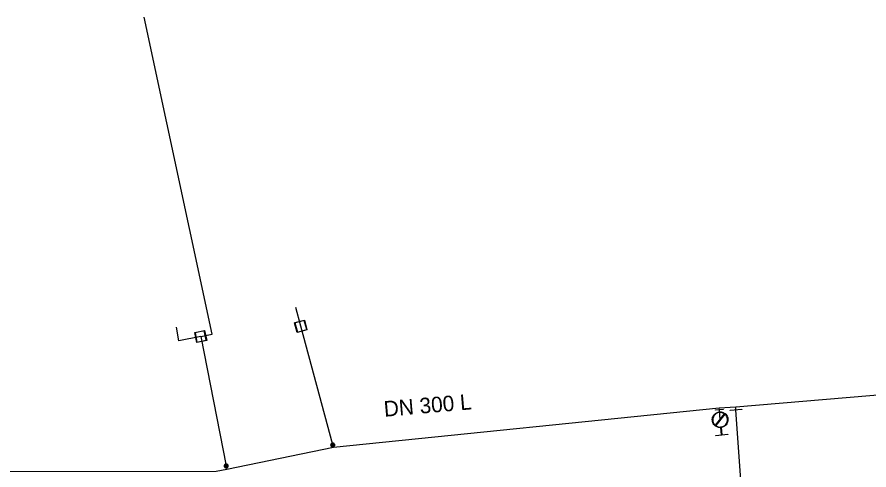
# Model space of a CAD drawing. Extents: x -832382 to -831581, y -1074670 to -1074251.
# Drawn here: x -831981.6 to -831872.2, y -1074329 to -1074270.9 of the extents above; entities that cross this region are included whole.
import ezdxf

# ---------------------------------------------------------------- set-up
doc = ezdxf.new("R2010")
doc.units = 0
for name, color, linetype in [('Hyd-odbočka', 7, 'Continuous'), ('Hyd-šoupě', 7, 'Continuous'), ('Hydrant', 7, 'Continuous'), ('Přípojka vodovodu', 7, 'Continuous'), ('Přípojkový uzávěr', 7, 'Continuous'), ('Roz-řad', 7, 'Continuous'), ('Roz-řad-popis základní', 7, 'Continuous'), ('Řad-šoupě', 7, 'Continuous'), ('Šachta vodovodní', 7, 'Continuous')]:
    doc.layers.add(name, color=color, linetype=linetype)

msp = doc.modelspace()

# ---------------------------------------------------------------- linework, layer by layer
at = {"layer": 'Hyd-odbočka'}
for p, q in [((-831891.44, -1074321.27), (-831891.46, -1074321.09)), ((-831891.35, -1074322.57), (-831891.44, -1074321.27))]:
    msp.add_line(p, q, dxfattribs=at)
at = {"layer": 'Hyd-šoupě'}
msp.add_lwpolyline([(-831891.94, -1074321.29), (-831890.94, -1074321.22), (-831890.94, -1074321.25), (-831891.94, -1074321.32), (-831891.94, -1074321.29)], dxfattribs=at)
at = {"layer": 'Hydrant'}
for points in [[(-831891.96, -1074323.28), (-831890.78, -1074321.82)], [(-831890.74, -1074321.86), (-831891.92, -1074323.32)], [(-831891.21, -1074323.56), (-831891.12, -1074324.49), (-831890.37, -1074324.41), (-831890.36, -1074324.48), (-831891.92, -1074324.64), (-831891.92, -1074324.58), (-831891.18, -1074324.5), (-831891.28, -1074323.57)]]:
    msp.add_lwpolyline(points, dxfattribs=at)
for points in [[(-831891.28, -1074323.57), (-831891.51, -1074323.58), (-831891.75, -1074323.49), (-831892, -1074323.38), (-831892.16, -1074323.16), (-831892.32, -1074322.94), (-831892.34, -1074322.68), (-831892.37, -1074322.42), (-831892.27, -1074322.17), (-831892.16, -1074321.92), (-831891.94, -1074321.76), (-831891.71, -1074321.6), (-831891.46, -1074321.58), (-831891.2, -1074321.55), (-831890.95, -1074321.65), (-831890.7, -1074321.76), (-831890.54, -1074321.98), (-831890.38, -1074322.21), (-831890.36, -1074322.46), (-831890.33, -1074322.73), (-831890.44, -1074322.98), (-831890.55, -1074323.23), (-831890.77, -1074323.38), (-831890.98, -1074323.53), (-831891.21, -1074323.56)], [(-831890.78, -1074321.82), (-831890.87, -1074321.76), (-831890.97, -1074321.71), (-831891.21, -1074321.61), (-831891.45, -1074321.64), (-831891.69, -1074321.66), (-831891.9, -1074321.81), (-831892.11, -1074321.96), (-831892.21, -1074322.19), (-831892.31, -1074322.43), (-831892.28, -1074322.67), (-831892.26, -1074322.91), (-831892.11, -1074323.12), (-831892.04, -1074323.21), (-831891.96, -1074323.28)], [(-831891.92, -1074323.32), (-831891.83, -1074323.39), (-831891.72, -1074323.43), (-831891.49, -1074323.53), (-831891.25, -1074323.5), (-831891.02, -1074323.48), (-831890.81, -1074323.33), (-831890.6, -1074323.19), (-831890.49, -1074322.95), (-831890.39, -1074322.72), (-831890.42, -1074322.47), (-831890.44, -1074322.23), (-831890.59, -1074322.02), (-831890.65, -1074321.93), (-831890.74, -1074321.86)]]:
    msp.add_open_spline(points, degree=3, dxfattribs=at)
at = {"layer": 'Přípojka vodovodu'}
for p, q in [((-831956.59, -1074311.57), (-831965.3, -1074270.86)), ((-831945.19, -1074310.57), (-831945.84, -1074308.15)), ((-831960.87, -1074312.43), (-831961.17, -1074310.68)), ((-831958.05, -1074311.87), (-831960.87, -1074312.43)), ((-831958.05, -1074311.87), (-831956.59, -1074311.57))]:
    msp.add_line(p, q, dxfattribs=at)
for points in [[(-831941.01, -1074326.13), (-831941.09, -1074325.81), (-831945.19, -1074310.57)], [(-831958.05, -1074311.87), (-831954.77, -1074328.5), (-831954.69, -1074328.95)]]:
    msp.add_lwpolyline(points, dxfattribs=at)
at = {"layer": 'Přípojkový uzávěr'}
for points in [[(-831941.09, -1074325.56), (-831941.03, -1074325.56), (-831940.97, -1074325.6), (-831940.91, -1074325.63), (-831940.87, -1074325.69), (-831940.84, -1074325.75), (-831940.84, -1074325.81), (-831940.84, -1074325.88), (-831940.87, -1074325.94), (-831940.91, -1074326), (-831940.97, -1074326.03), (-831941.03, -1074326.06), (-831941.09, -1074326.06), (-831941.15, -1074326.06), (-831941.21, -1074326.03), (-831941.27, -1074326), (-831941.31, -1074325.94), (-831941.34, -1074325.88), (-831941.34, -1074325.81), (-831941.34, -1074325.75), (-831941.31, -1074325.69), (-831941.27, -1074325.63), (-831941.21, -1074325.6), (-831941.15, -1074325.56), (-831941.09, -1074325.56)], [(-831941.09, -1074325.59), (-831941.15, -1074325.59), (-831941.2, -1074325.62), (-831941.26, -1074325.65), (-831941.29, -1074325.7), (-831941.32, -1074325.75), (-831941.32, -1074325.81), (-831941.32, -1074325.87), (-831941.29, -1074325.93), (-831941.26, -1074325.98), (-831941.2, -1074326.01), (-831941.15, -1074326.04), (-831941.09, -1074326.04), (-831941.03, -1074326.04), (-831940.98, -1074326.01), (-831940.92, -1074325.98), (-831940.89, -1074325.93), (-831940.86, -1074325.87), (-831940.86, -1074325.81), (-831940.86, -1074325.75), (-831940.89, -1074325.7), (-831940.92, -1074325.65), (-831940.98, -1074325.62), (-831941.03, -1074325.59), (-831941.09, -1074325.59)], [(-831941.09, -1074325.6), (-831941.04, -1074325.6), (-831940.99, -1074325.63), (-831940.94, -1074325.66), (-831940.91, -1074325.71), (-831940.88, -1074325.76), (-831940.88, -1074325.81), (-831940.88, -1074325.87), (-831940.91, -1074325.92), (-831940.94, -1074325.97), (-831940.99, -1074326), (-831941.04, -1074326.02), (-831941.09, -1074326.02), (-831941.14, -1074326.02), (-831941.19, -1074326), (-831941.24, -1074325.97), (-831941.27, -1074325.92), (-831941.3, -1074325.87), (-831941.3, -1074325.81), (-831941.3, -1074325.76), (-831941.27, -1074325.71), (-831941.24, -1074325.66), (-831941.19, -1074325.63), (-831941.14, -1074325.6), (-831941.09, -1074325.6)], [(-831941.09, -1074325.63), (-831941.17, -1074325.63), (-831941.22, -1074325.68), (-831941.28, -1074325.74), (-831941.28, -1074325.81), (-831941.28, -1074325.89), (-831941.22, -1074325.95), (-831941.17, -1074326), (-831941.09, -1074326), (-831941.01, -1074326), (-831940.96, -1074325.95), (-831940.9, -1074325.89), (-831940.9, -1074325.81), (-831940.9, -1074325.74), (-831940.96, -1074325.68), (-831941.01, -1074325.63), (-831941.09, -1074325.63)], [(-831941.09, -1074325.65), (-831941.02, -1074325.65), (-831940.97, -1074325.7), (-831940.93, -1074325.74), (-831940.93, -1074325.81), (-831940.93, -1074325.88), (-831940.97, -1074325.93), (-831941.02, -1074325.98), (-831941.09, -1074325.98), (-831941.16, -1074325.98), (-831941.21, -1074325.93), (-831941.25, -1074325.88), (-831941.25, -1074325.81), (-831941.25, -1074325.74), (-831941.21, -1074325.7), (-831941.16, -1074325.65), (-831941.09, -1074325.65)], [(-831941.09, -1074325.67), (-831941.15, -1074325.67), (-831941.19, -1074325.71), (-831941.23, -1074325.75), (-831941.23, -1074325.81), (-831941.23, -1074325.87), (-831941.19, -1074325.92), (-831941.15, -1074325.96), (-831941.09, -1074325.96), (-831941.03, -1074325.96), (-831940.99, -1074325.92), (-831940.95, -1074325.87), (-831940.95, -1074325.81), (-831940.95, -1074325.75), (-831940.99, -1074325.71), (-831941.03, -1074325.67), (-831941.09, -1074325.67)], [(-831941.09, -1074325.69), (-831941.04, -1074325.69), (-831941, -1074325.73), (-831940.97, -1074325.76), (-831940.97, -1074325.81), (-831940.97, -1074325.87), (-831941, -1074325.9), (-831941.04, -1074325.94), (-831941.09, -1074325.94), (-831941.14, -1074325.94), (-831941.18, -1074325.9), (-831941.22, -1074325.87), (-831941.22, -1074325.81), (-831941.22, -1074325.76), (-831941.18, -1074325.73), (-831941.14, -1074325.69), (-831941.09, -1074325.69)], [(-831941.09, -1074325.71), (-831941.13, -1074325.71), (-831941.16, -1074325.74), (-831941.19, -1074325.77), (-831941.19, -1074325.81), (-831941.19, -1074325.86), (-831941.16, -1074325.89), (-831941.13, -1074325.91), (-831941.09, -1074325.91), (-831941.05, -1074325.91), (-831941.02, -1074325.89), (-831940.99, -1074325.86), (-831940.99, -1074325.81), (-831940.99, -1074325.77), (-831941.02, -1074325.74), (-831941.05, -1074325.71), (-831941.09, -1074325.71)], [(-831941.09, -1074325.73), (-831941.06, -1074325.73), (-831941.03, -1074325.75), (-831941.01, -1074325.78), (-831941.01, -1074325.81), (-831941.01, -1074325.85), (-831941.03, -1074325.87), (-831941.06, -1074325.9), (-831941.09, -1074325.9), (-831941.13, -1074325.9), (-831941.15, -1074325.87), (-831941.17, -1074325.85), (-831941.17, -1074325.81), (-831941.17, -1074325.78), (-831941.15, -1074325.75), (-831941.13, -1074325.73), (-831941.09, -1074325.73)], [(-831941.09, -1074325.75), (-831941.12, -1074325.75), (-831941.13, -1074325.77), (-831941.15, -1074325.79), (-831941.15, -1074325.81), (-831941.15, -1074325.84), (-831941.13, -1074325.86), (-831941.12, -1074325.88), (-831941.09, -1074325.88), (-831941.06, -1074325.88), (-831941.05, -1074325.86), (-831941.03, -1074325.84), (-831941.03, -1074325.81), (-831941.03, -1074325.79), (-831941.05, -1074325.77), (-831941.06, -1074325.75), (-831941.09, -1074325.75)], [(-831941.09, -1074325.77), (-831941.07, -1074325.77), (-831941.06, -1074325.79), (-831941.05, -1074325.8), (-831941.05, -1074325.81), (-831941.05, -1074325.83), (-831941.06, -1074325.84), (-831941.07, -1074325.85), (-831941.09, -1074325.85), (-831941.11, -1074325.85), (-831941.12, -1074325.84), (-831941.13, -1074325.83), (-831941.13, -1074325.81), (-831941.13, -1074325.8), (-831941.12, -1074325.79), (-831941.11, -1074325.77), (-831941.09, -1074325.77)], [(-831941.09, -1074325.79), (-831941.1, -1074325.79), (-831941.11, -1074325.8), (-831941.11, -1074325.8), (-831941.11, -1074325.81), (-831941.11, -1074325.82), (-831941.11, -1074325.83), (-831941.1, -1074325.84), (-831941.09, -1074325.84), (-831941.08, -1074325.84), (-831941.07, -1074325.83), (-831941.07, -1074325.82), (-831941.07, -1074325.81), (-831941.07, -1074325.8), (-831941.07, -1074325.8), (-831941.08, -1074325.79), (-831941.09, -1074325.79)], [(-831954.77, -1074328.25), (-831954.71, -1074328.25), (-831954.65, -1074328.28), (-831954.59, -1074328.32), (-831954.56, -1074328.38), (-831954.52, -1074328.44), (-831954.52, -1074328.5), (-831954.52, -1074328.57), (-831954.56, -1074328.63), (-831954.59, -1074328.68), (-831954.65, -1074328.72), (-831954.71, -1074328.75), (-831954.77, -1074328.75), (-831954.84, -1074328.75), (-831954.9, -1074328.72), (-831954.96, -1074328.68), (-831954.99, -1074328.63), (-831955.02, -1074328.57), (-831955.02, -1074328.5), (-831955.02, -1074328.44), (-831954.99, -1074328.38), (-831954.96, -1074328.32), (-831954.9, -1074328.28), (-831954.84, -1074328.25), (-831954.77, -1074328.25)], [(-831954.77, -1074328.27), (-831954.83, -1074328.27), (-831954.89, -1074328.3), (-831954.94, -1074328.33), (-831954.97, -1074328.39), (-831955, -1074328.44), (-831955, -1074328.5), (-831955, -1074328.56), (-831954.97, -1074328.61), (-831954.94, -1074328.67), (-831954.89, -1074328.7), (-831954.83, -1074328.73), (-831954.77, -1074328.73), (-831954.72, -1074328.73), (-831954.66, -1074328.7), (-831954.61, -1074328.67), (-831954.58, -1074328.61), (-831954.55, -1074328.56), (-831954.55, -1074328.5), (-831954.55, -1074328.44), (-831954.58, -1074328.39), (-831954.61, -1074328.33), (-831954.66, -1074328.3), (-831954.72, -1074328.27), (-831954.77, -1074328.27)], [(-831954.77, -1074328.29), (-831954.72, -1074328.29), (-831954.67, -1074328.32), (-831954.62, -1074328.35), (-831954.59, -1074328.4), (-831954.56, -1074328.45), (-831954.56, -1074328.5), (-831954.56, -1074328.56), (-831954.59, -1074328.61), (-831954.62, -1074328.66), (-831954.67, -1074328.68), (-831954.72, -1074328.71), (-831954.77, -1074328.71), (-831954.83, -1074328.71), (-831954.88, -1074328.68), (-831954.93, -1074328.66), (-831954.96, -1074328.61), (-831954.98, -1074328.56), (-831954.98, -1074328.5), (-831954.98, -1074328.45), (-831954.96, -1074328.4), (-831954.93, -1074328.35), (-831954.88, -1074328.32), (-831954.83, -1074328.29), (-831954.77, -1074328.29)], [(-831954.77, -1074328.31), (-831954.85, -1074328.31), (-831954.91, -1074328.37), (-831954.96, -1074328.42), (-831954.96, -1074328.5), (-831954.96, -1074328.58), (-831954.91, -1074328.63), (-831954.85, -1074328.69), (-831954.77, -1074328.69), (-831954.7, -1074328.69), (-831954.64, -1074328.63), (-831954.59, -1074328.58), (-831954.59, -1074328.5), (-831954.59, -1074328.42), (-831954.64, -1074328.37), (-831954.7, -1074328.31), (-831954.77, -1074328.31)], [(-831954.77, -1074328.34), (-831954.71, -1074328.34), (-831954.66, -1074328.38), (-831954.61, -1074328.43), (-831954.61, -1074328.5), (-831954.61, -1074328.57), (-831954.66, -1074328.62), (-831954.71, -1074328.66), (-831954.77, -1074328.66), (-831954.84, -1074328.66), (-831954.89, -1074328.62), (-831954.94, -1074328.57), (-831954.94, -1074328.5), (-831954.94, -1074328.43), (-831954.89, -1074328.38), (-831954.84, -1074328.34), (-831954.77, -1074328.34)], [(-831954.77, -1074328.36), (-831954.83, -1074328.36), (-831954.88, -1074328.4), (-831954.92, -1074328.44), (-831954.92, -1074328.5), (-831954.92, -1074328.56), (-831954.88, -1074328.6), (-831954.83, -1074328.64), (-831954.77, -1074328.64), (-831954.71, -1074328.64), (-831954.67, -1074328.6), (-831954.63, -1074328.56), (-831954.63, -1074328.5), (-831954.63, -1074328.44), (-831954.67, -1074328.4), (-831954.71, -1074328.36), (-831954.77, -1074328.36)], [(-831954.77, -1074328.38), (-831954.72, -1074328.38), (-831954.69, -1074328.41), (-831954.65, -1074328.45), (-831954.65, -1074328.5), (-831954.65, -1074328.55), (-831954.69, -1074328.59), (-831954.72, -1074328.63), (-831954.77, -1074328.63), (-831954.83, -1074328.63), (-831954.86, -1074328.59), (-831954.9, -1074328.55), (-831954.9, -1074328.5), (-831954.9, -1074328.45), (-831954.86, -1074328.41), (-831954.83, -1074328.38), (-831954.77, -1074328.38)], [(-831954.77, -1074328.4), (-831954.82, -1074328.4), (-831954.85, -1074328.43), (-831954.88, -1074328.46), (-831954.88, -1074328.5), (-831954.88, -1074328.54), (-831954.85, -1074328.57), (-831954.82, -1074328.6), (-831954.77, -1074328.6), (-831954.73, -1074328.6), (-831954.7, -1074328.57), (-831954.67, -1074328.54), (-831954.67, -1074328.5), (-831954.67, -1074328.46), (-831954.7, -1074328.43), (-831954.73, -1074328.4), (-831954.77, -1074328.4)], [(-831954.77, -1074328.42), (-831954.74, -1074328.42), (-831954.71, -1074328.44), (-831954.69, -1074328.47), (-831954.69, -1074328.5), (-831954.69, -1074328.54), (-831954.71, -1074328.56), (-831954.74, -1074328.58), (-831954.77, -1074328.58), (-831954.81, -1074328.58), (-831954.83, -1074328.56), (-831954.86, -1074328.54), (-831954.86, -1074328.5), (-831954.86, -1074328.47), (-831954.83, -1074328.44), (-831954.81, -1074328.42), (-831954.77, -1074328.42)], [(-831954.77, -1074328.44), (-831954.8, -1074328.44), (-831954.82, -1074328.46), (-831954.84, -1074328.48), (-831954.84, -1074328.5), (-831954.84, -1074328.53), (-831954.82, -1074328.55), (-831954.8, -1074328.56), (-831954.77, -1074328.56), (-831954.75, -1074328.56), (-831954.73, -1074328.55), (-831954.71, -1074328.53), (-831954.71, -1074328.5), (-831954.71, -1074328.48), (-831954.73, -1074328.46), (-831954.75, -1074328.44), (-831954.77, -1074328.44)], [(-831954.77, -1074328.46), (-831954.76, -1074328.46), (-831954.75, -1074328.47), (-831954.74, -1074328.48), (-831954.74, -1074328.5), (-831954.74, -1074328.52), (-831954.75, -1074328.53), (-831954.76, -1074328.54), (-831954.77, -1074328.54), (-831954.79, -1074328.54), (-831954.8, -1074328.53), (-831954.81, -1074328.52), (-831954.81, -1074328.5), (-831954.81, -1074328.48), (-831954.8, -1074328.47), (-831954.79, -1074328.46), (-831954.77, -1074328.46)], [(-831954.77, -1074328.48), (-831954.78, -1074328.48), (-831954.79, -1074328.48), (-831954.8, -1074328.49), (-831954.8, -1074328.5), (-831954.8, -1074328.51), (-831954.79, -1074328.52), (-831954.78, -1074328.52), (-831954.77, -1074328.52), (-831954.76, -1074328.52), (-831954.76, -1074328.52), (-831954.75, -1074328.51), (-831954.75, -1074328.5), (-831954.75, -1074328.49), (-831954.76, -1074328.48), (-831954.76, -1074328.48), (-831954.77, -1074328.48)]]:
    msp.add_open_spline(points, degree=3, dxfattribs=at)
at = {"layer": 'Roz-řad'}
msp.add_line((-831889.32, -1074321.29), (-831889.35, -1074320.97), dxfattribs=at)
for points in [[(-831856.5, -1074307.38), (-831854.91, -1074318.03), (-831889.35, -1074320.97)], [(-831889.35, -1074320.97), (-831891.46, -1074321.09), (-831941.01, -1074326.13), (-831954.69, -1074328.95), (-831955.38, -1074329.09), (-831956.08, -1074329.23), (-832023.14, -1074329.26), (-832023.3, -1074323.91), (-832030.6, -1074322.53), (-832052.1, -1074319.75), (-832063.16, -1074318.14), (-832094.86, -1074326.92), (-832088.78, -1074393.24), (-832128.55, -1074415.63), (-832220.51, -1074467.41), (-832382.46, -1074558.59)], [(-831886.3, -1074408.64), (-831880.97, -1074408.01), (-831882.04, -1074380.26), (-831888.26, -1074367.1), (-831888.25, -1074366.76), (-831887.64, -1074355.49), (-831887.73, -1074344.47), (-831887.76, -1074343.52), (-831889.32, -1074321.29)]]:
    msp.add_lwpolyline(points, dxfattribs=at)
at = {"layer": 'Řad-šoupě'}
msp.add_lwpolyline([(-831888.57, -1074321.25), (-831890.07, -1074321.38), (-831890.07, -1074321.33), (-831888.58, -1074321.2), (-831888.57, -1074321.25)], dxfattribs=at)
at = {"layer": 'Šachta vodovodní'}
for points in [[(-831945.99, -1074310.11), (-831944.73, -1074309.77), (-831944.4, -1074311.03), (-831945.65, -1074311.37), (-831945.99, -1074310.11)], [(-831945.62, -1074311.32), (-831944.44, -1074311), (-831944.76, -1074309.82), (-831945.94, -1074310.14), (-831945.62, -1074311.32)], [(-831957.55, -1074311.11), (-831957.28, -1074312.38), (-831958.56, -1074312.64), (-831958.82, -1074311.37), (-831957.55, -1074311.11)], [(-831958.77, -1074311.4), (-831958.53, -1074312.59), (-831957.33, -1074312.35), (-831957.58, -1074311.15), (-831958.77, -1074311.4)]]:
    msp.add_lwpolyline(points, dxfattribs=at)

# ---------------------------------------------------------------- texts
at = {"layer": 'Roz-řad-popis základní'}
msp.add_text('DN 300 L', height=2, rotation=4.8833, dxfattribs=at).set_placement((-831934.45, -1074322.19))

doc.saveas('drawing.dxf')
